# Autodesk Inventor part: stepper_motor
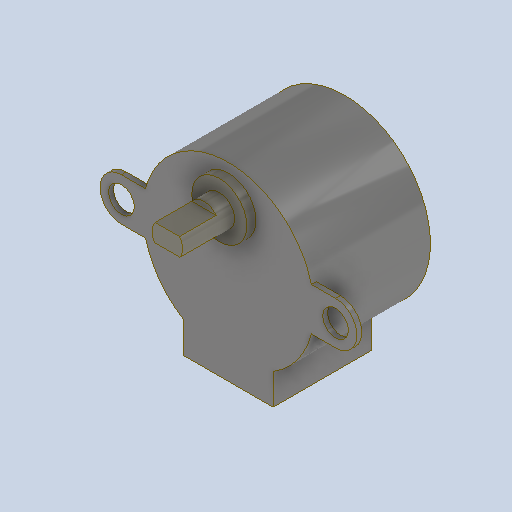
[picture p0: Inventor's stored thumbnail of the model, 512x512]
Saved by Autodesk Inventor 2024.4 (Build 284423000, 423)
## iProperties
Created: 2025-07
Part Number: stepper_motor
Material: Generic
Document SubType Name: Modeling
Designer: AdminForWorker
Density: 1 g/cm^3
Appearance: Default
Title: stepper_motor v3
Author: AdminForWorker
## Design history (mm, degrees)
feature "Body1"
body "Solid1"
